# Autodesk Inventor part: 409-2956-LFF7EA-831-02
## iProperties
Created: 2010-09
Part Number: 409-2956-LFF7EA-831-02
Material: 3/8"OD TUBE - SS
Document SubType Name: Modeling
Designer: S. Boerckel
Engineer: Steve Boerckel
Mass: 166.544 g
Surface Area: 342.312 cm^2
Volume: 20.6119 cm^3
Density: 8.08 g/cm^3
Description: LOW PRESSURE GAUGE TUBE
LGTH: 21.184 in
Author: S. Boerckel
Revision Number: 0
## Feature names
1. Sweep1
